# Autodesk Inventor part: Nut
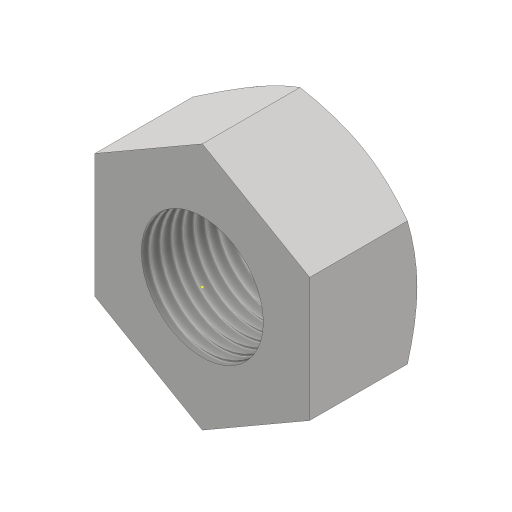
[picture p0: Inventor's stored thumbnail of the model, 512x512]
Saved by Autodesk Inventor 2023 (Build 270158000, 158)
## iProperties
Created: 2016-05
Part Number: Nut
Material: Generic
Document SubType Name: Modeling
Designer: CADCIM
Density: 1 g/cm^3
Appearance: Default
Author: CADCIM
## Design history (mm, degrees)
sketch "Sketch1"
  geometry: L1 (0, -33.255)-(-28.8, -16.628); L2 (-28.8, -16.628)-(-28.8, 16.628); L3 (-28.8, 16.628)-(0, 33.255); L4 (0, 33.255)-(28.8, 16.628); L5 (28.8, 16.628)-(28.8, -16.628); L6 (28.8, -16.628)-(0, -33.255); 2 further points
  constraints: 12 end point, 1 coincident, 13 other
  dimensions: "d0" = 57.6 distance between parallel lines of L2 L5
extrude "Extrusion1" new body sketch "Sketch1" stored distance "d1" = 28.8; taper "d2" = 0 deg
sketch "Sketch2"
  geometry: L1 (0, 33.255)-(-28.8, 16.628) reference; C1 r 28.8 at (0, 0); 1 further point
  constraints: 1 centre point, 1 coincident, 1 tangent
extrude "Extrusion2" sketch "Sketch2" distance "d3" = 28.8; taper "d4" = 60 deg
sketch "Sketch3"
  geometry: 1 further point
hole "Hole1" diameter "d7" = 32.752; stored, may be unused: countersink angle "d11" = 90 deg, drill point angle "d13" = 118 deg; dims "d5" = 10, "d6" = 10, "d8" = 72, "d9" = 4, "d10" = 2, "d12" = 85.1
body "Solid1"
